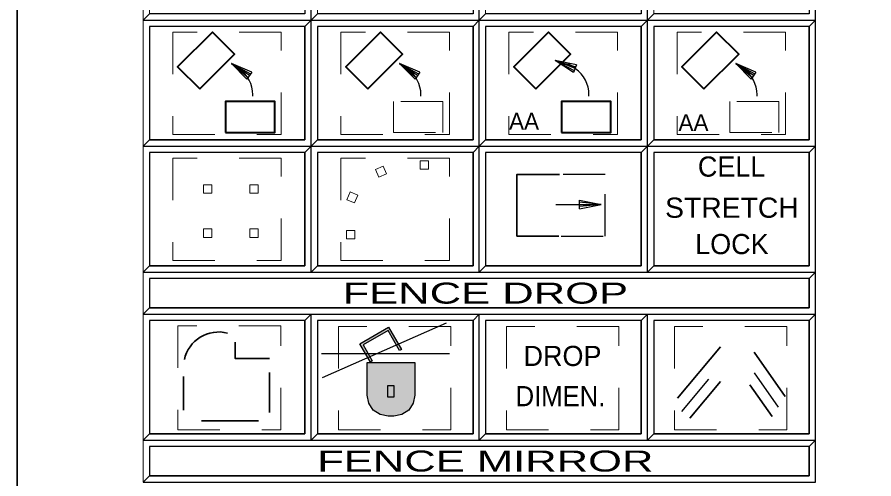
# Model space of a CAD drawing. Extents: x 95906.8 to 95923.6, y 90964.8 to 90972.8.
# Drawn here: x 95906.832 to 95908.871, y 90966.169 to 90967.269 of the extents above; entities that cross this region are included whole.
import ezdxf
from ezdxf.enums import TextEntityAlignment as Align

# ---------------------------------------------------------------- set-up
doc = ezdxf.new("R2010")
doc.units = 0
doc.header["$LTSCALE"] = 0.019
for name, pattern in [('DOT_DASHED', [7.7, 5, -1.2, 0.3, -1.2]), ('DOTTED', [1.5, 0.3, -1.2]), ('MEDIUM_DASHED', [4.5, 3, -1.5])]:
    doc.linetypes.add(name, pattern=pattern)
for name, color, linetype, lineweight in [('11', 7, 'Continuous', 25), ('12', 7, 'Continuous', 25), ('18', 7, 'Continuous', 25), ('2', 7, 'Continuous', 13), ('3', 7, 'Continuous', 25), ('6', 7, 'Continuous', 25), ('7', 7, 'Continuous', 35)]:
    doc.layers.add(name, color=color, linetype=linetype, lineweight=lineweight)

msp = doc.modelspace()

# ---------------------------------------------------------------- hatches: boundary and pattern name
at = {"layer": '6'}
for points in [[(95907.6731, 90966.4475), (95907.6478, 90966.4913), (95907.7164, 90966.5309), (95907.7471, 90966.4778), (95907.7424, 90966.4751), (95907.7152, 90966.5225), (95907.6556, 90966.4883), (95907.6776, 90966.4501)], [(95907.6653, 90966.3684), (95907.6653, 90966.4468), (95907.7788, 90966.4468), (95907.7788, 90966.3684), (95907.775, 90966.3493), (95907.7642, 90966.333), (95907.7479, 90966.3222), (95907.7288, 90966.3184), (95907.7153, 90966.3184), (95907.6962, 90966.3222), (95907.6799, 90966.333), (95907.6691, 90966.3493)], [(95907.7143, 90966.3914), (95907.7285, 90966.3914), (95907.7285, 90966.3638), (95907.7143, 90966.3638)]]:
    msp.add_hatch(color=256, dxfattribs=at).paths.add_polyline_path(points)

# ---------------------------------------------------------------- linework, layer by layer
at = {"layer": '11'}
for points in [[(95907.1473, 90966.9767), (95907.5173, 90966.9767), (95907.5173, 90967.2467), (95907.1473, 90967.2467)], [(95907.5473, 90966.9767), (95907.9173, 90966.9767), (95907.9173, 90967.2467), (95907.5473, 90967.2467)], [(95907.9473, 90966.9767), (95908.3173, 90966.9767), (95908.3173, 90967.2467), (95907.9473, 90967.2467)], [(95908.3473, 90966.9767), (95908.7173, 90966.9767), (95908.7173, 90967.2467), (95908.3473, 90967.2467)], [(95907.1473, 90966.6767), (95907.5173, 90966.6767), (95907.5173, 90966.9467), (95907.1473, 90966.9467)], [(95907.5473, 90966.6767), (95907.9173, 90966.6767), (95907.9173, 90966.9467), (95907.5473, 90966.9467)], [(95907.9473, 90966.6767), (95908.3173, 90966.6767), (95908.3173, 90966.9467), (95907.9473, 90966.9467)], [(95908.3473, 90966.6767), (95908.7173, 90966.6767), (95908.7173, 90966.9467), (95908.3473, 90966.9467)], [(95907.5473, 90966.2767), (95907.9173, 90966.2767), (95907.9173, 90966.5467), (95907.5473, 90966.5467)], [(95907.9473, 90966.2767), (95908.3173, 90966.2767), (95908.3173, 90966.5467), (95907.9473, 90966.5467)], [(95908.3473, 90966.2767), (95908.7173, 90966.2767), (95908.7173, 90966.5467), (95908.3473, 90966.5467)]]:
    msp.add_lwpolyline(points, close=True, dxfattribs=at)
at = {"layer": '12'}
msp.add_lwpolyline([(95907.1473, 90966.2767), (95907.5173, 90966.2767), (95907.5173, 90966.5467), (95907.1473, 90966.5467)], close=True, dxfattribs=at)
at = {"layer": '18'}
for points in [[(95907.1473, 90966.5767), (95908.7173, 90966.5767), (95908.7173, 90966.6467), (95907.1473, 90966.6467)], [(95907.1473, 90966.1767), (95908.7173, 90966.1767), (95908.7173, 90966.2467), (95907.1473, 90966.2467)]]:
    msp.add_lwpolyline(points, close=True, dxfattribs=at)
at = {"layer": '2'}
for points in [[(95907.1323, 90967.5617), (95907.1323, 90967.2617), (95907.1473, 90967.2767), (95907.1473, 90967.5467), (95907.5173, 90967.5467), (95907.5323, 90967.5617)], [(95907.5323, 90967.5617), (95907.5323, 90967.2617), (95907.5473, 90967.2767), (95907.5473, 90967.5467), (95907.9173, 90967.5467), (95907.9323, 90967.5617)], [(95907.9323, 90967.5617), (95907.9323, 90967.2617), (95907.9473, 90967.2767), (95907.9473, 90967.5467), (95908.3173, 90967.5467), (95908.3323, 90967.5617)], [(95908.3323, 90967.5617), (95908.3323, 90967.2617), (95908.3473, 90967.2767), (95908.3473, 90967.5467), (95908.7173, 90967.5467), (95908.7323, 90967.5617)], [(95907.1323, 90967.2617), (95907.1323, 90966.9617), (95907.1473, 90966.9767), (95907.1473, 90967.2467), (95907.5173, 90967.2467), (95907.5323, 90967.2617)], [(95907.5323, 90967.2617), (95907.5323, 90966.9617), (95907.5473, 90966.9767), (95907.5473, 90967.2467), (95907.9173, 90967.2467), (95907.9323, 90967.2617)], [(95907.9323, 90967.2617), (95907.9323, 90966.9617), (95907.9473, 90966.9767), (95907.9473, 90967.2467), (95908.3173, 90967.2467), (95908.3323, 90967.2617)], [(95908.3323, 90967.2617), (95908.3323, 90966.9617), (95908.3473, 90966.9767), (95908.3473, 90967.2467), (95908.7173, 90967.2467), (95908.7323, 90967.2617)], [(95907.1323, 90966.9617), (95907.1323, 90966.6617), (95907.1473, 90966.6767), (95907.1473, 90966.9467), (95907.5173, 90966.9467), (95907.5323, 90966.9617)], [(95907.5323, 90966.9617), (95907.5323, 90966.6617), (95907.5473, 90966.6767), (95907.5473, 90966.9467), (95907.9173, 90966.9467), (95907.9323, 90966.9617)], [(95907.9323, 90966.9617), (95907.9323, 90966.6617), (95907.9473, 90966.6767), (95907.9473, 90966.9467), (95908.3173, 90966.9467), (95908.3323, 90966.9617)], [(95908.3323, 90966.9617), (95908.3323, 90966.6617), (95908.3473, 90966.6767), (95908.3473, 90966.9467), (95908.7173, 90966.9467), (95908.7323, 90966.9617)], [(95907.1323, 90966.6617), (95907.1323, 90966.5617), (95907.1473, 90966.5767), (95907.1473, 90966.6467), (95908.7173, 90966.6467), (95908.7323, 90966.6617)], [(95907.1323, 90966.5617), (95907.1323, 90966.2617), (95907.1473, 90966.2767), (95907.1473, 90966.5467), (95907.5173, 90966.5467), (95907.5323, 90966.5617)], [(95907.5323, 90966.5617), (95907.5323, 90966.2617), (95907.5473, 90966.2767), (95907.5473, 90966.5467), (95907.9173, 90966.5467), (95907.9323, 90966.5617)], [(95907.9323, 90966.5617), (95907.9323, 90966.2617), (95907.9473, 90966.2767), (95907.9473, 90966.5467), (95908.3173, 90966.5467), (95908.3323, 90966.5617)], [(95908.3323, 90966.5617), (95908.3323, 90966.2617), (95908.3473, 90966.2767), (95908.3473, 90966.5467), (95908.7173, 90966.5467), (95908.7323, 90966.5617)], [(95907.1323, 90966.2617), (95907.1323, 90966.1617), (95907.1473, 90966.1767), (95907.1473, 90966.2467), (95908.7173, 90966.2467), (95908.7323, 90966.2617)]]:
    msp.add_lwpolyline(points, close=True, dxfattribs=at)
at = {"layer": '3'}
for points in [[(95907.1323, 90967.2617), (95907.5323, 90967.2617), (95907.5323, 90967.5617), (95907.5173, 90967.5467), (95907.5173, 90967.2767), (95907.1473, 90967.2767)], [(95907.5323, 90967.2617), (95907.9323, 90967.2617), (95907.9323, 90967.5617), (95907.9173, 90967.5467), (95907.9173, 90967.2767), (95907.5473, 90967.2767)], [(95907.9323, 90967.2617), (95908.3323, 90967.2617), (95908.3323, 90967.5617), (95908.3173, 90967.5467), (95908.3173, 90967.2767), (95907.9473, 90967.2767)], [(95908.3323, 90967.2617), (95908.7323, 90967.2617), (95908.7323, 90967.5617), (95908.7173, 90967.5467), (95908.7173, 90967.2767), (95908.3473, 90967.2767)], [(95907.1323, 90966.9617), (95907.5323, 90966.9617), (95907.5323, 90967.2617), (95907.5173, 90967.2467), (95907.5173, 90966.9767), (95907.1473, 90966.9767)], [(95907.5323, 90966.9617), (95907.9323, 90966.9617), (95907.9323, 90967.2617), (95907.9173, 90967.2467), (95907.9173, 90966.9767), (95907.5473, 90966.9767)], [(95907.9323, 90966.9617), (95908.3323, 90966.9617), (95908.3323, 90967.2617), (95908.3173, 90967.2467), (95908.3173, 90966.9767), (95907.9473, 90966.9767)], [(95908.3323, 90966.9617), (95908.7323, 90966.9617), (95908.7323, 90967.2617), (95908.7173, 90967.2467), (95908.7173, 90966.9767), (95908.3473, 90966.9767)], [(95907.1323, 90966.6617), (95907.5323, 90966.6617), (95907.5323, 90966.9617), (95907.5173, 90966.9467), (95907.5173, 90966.6767), (95907.1473, 90966.6767)], [(95907.5323, 90966.6617), (95907.9323, 90966.6617), (95907.9323, 90966.9617), (95907.9173, 90966.9467), (95907.9173, 90966.6767), (95907.5473, 90966.6767)], [(95907.9323, 90966.6617), (95908.3323, 90966.6617), (95908.3323, 90966.9617), (95908.3173, 90966.9467), (95908.3173, 90966.6767), (95907.9473, 90966.6767)], [(95908.3323, 90966.6617), (95908.7323, 90966.6617), (95908.7323, 90966.9617), (95908.7173, 90966.9467), (95908.7173, 90966.6767), (95908.3473, 90966.6767)], [(95907.1323, 90966.5617), (95908.7323, 90966.5617), (95908.7323, 90966.6617), (95908.7173, 90966.6467), (95908.7173, 90966.5767), (95907.1473, 90966.5767)], [(95907.1323, 90966.2617), (95907.5323, 90966.2617), (95907.5323, 90966.5617), (95907.5173, 90966.5467), (95907.5173, 90966.2767), (95907.1473, 90966.2767)], [(95907.5323, 90966.2617), (95907.9323, 90966.2617), (95907.9323, 90966.5617), (95907.9173, 90966.5467), (95907.9173, 90966.2767), (95907.5473, 90966.2767)], [(95907.9323, 90966.2617), (95908.3323, 90966.2617), (95908.3323, 90966.5617), (95908.3173, 90966.5467), (95908.3173, 90966.2767), (95907.9473, 90966.2767)], [(95908.3323, 90966.2617), (95908.7323, 90966.2617), (95908.7323, 90966.5617), (95908.7173, 90966.5467), (95908.7173, 90966.2767), (95908.3473, 90966.2767)], [(95907.1323, 90966.1617), (95908.7323, 90966.1617), (95908.7323, 90966.2617), (95908.7173, 90966.2467), (95908.7173, 90966.1767), (95907.1473, 90966.1767)]]:
    msp.add_lwpolyline(points, close=True, dxfattribs=at)
at = {"layer": '6'}
for p, q in [((95907.361, 90967.1461), (95907.3426, 90967.1585)), ((95907.3851, 90967.1299), (95907.3426, 90967.1585)), ((95907.3426, 90967.1585), (95907.3877, 90967.1338)), ((95907.761, 90967.1461), (95907.7426, 90967.1585)), ((95907.7851, 90967.1299), (95907.7426, 90967.1585)), ((95907.7426, 90967.1585), (95907.7877, 90967.1338)), ((95908.1601, 90967.1465), (95908.1128, 90967.1662)), ((95908.1128, 90967.1662), (95908.1619, 90967.1509)), ((95908.161, 90967.1461), (95908.1426, 90967.1585)), ((95908.561, 90967.1461), (95908.5426, 90967.1585)), ((95908.5851, 90967.1299), (95908.5426, 90967.1585)), ((95908.5426, 90967.1585), (95908.5877, 90967.1338)), ((95907.3933, 90967.081), (95907.3933, 90967.0844)), ((95907.7933, 90967.081), (95907.7933, 90967.0844)), ((95908.1933, 90967.081), (95908.1933, 90967.0844)), ((95908.5933, 90967.081), (95908.5933, 90967.0844)), ((95908.1146, 90966.823), (95908.2221, 90966.823)), ((95908.1709, 90966.823), (95908.2221, 90966.823)), ((95908.2221, 90966.823), (95908.1709, 90966.8182)), ((95907.559, 90966.4108), (95907.8542, 90966.541)), ((95907.8613, 90966.467), (95907.5569, 90966.467))]:
    msp.add_line(p, q, dxfattribs=at)
at = {"layer": '6', "lineweight": 35}
for p, q in [((95908.404, 90966.3615), (95908.5067, 90966.4839)), ((95908.5862, 90966.4713), (95908.6601, 90966.3657)), ((95907.2284, 90966.3332), (95907.2284, 90966.4131)), ((95907.4328, 90966.4223), (95907.4328, 90966.327)), ((95908.4335, 90966.3142), (95908.5067, 90966.4015)), ((95908.5763, 90966.3931), (95908.629, 90966.3178)), ((95907.4067, 90966.3071), (95907.2714, 90966.3071))]:
    msp.add_line(p, q, dxfattribs=at)
at = {"layer": '6', "linetype": 'DOT_DASHED'}
for p, q in [((95908.4147, 90966.3299), (95908.5067, 90966.4396)), ((95908.5862, 90966.4217), (95908.6491, 90966.3319))]:
    msp.add_line(p, q, dxfattribs=at)
at = {"layer": '6', "linetype": 'DOTTED', "lineweight": 13}
for points in [[(95907.2029, 90966.9893), (95907.4611, 90966.9893), (95907.4611, 90967.2332), (95907.2029, 90967.2332)], [(95907.6029, 90966.9893), (95907.8611, 90966.9893), (95907.8611, 90967.2332), (95907.6029, 90967.2332)], [(95908.0029, 90966.9893), (95908.2611, 90966.9893), (95908.2611, 90967.2332), (95908.0029, 90967.2332)], [(95908.4029, 90966.9893), (95908.6611, 90966.9893), (95908.6611, 90967.2332), (95908.4029, 90967.2332)], [(95907.2029, 90966.6893), (95907.4611, 90966.6893), (95907.4611, 90966.9332), (95907.2029, 90966.9332)], [(95907.6029, 90966.6893), (95907.8611, 90966.6893), (95907.8611, 90966.9332), (95907.6029, 90966.9332)], [(95907.2145, 90966.2863), (95907.46, 90966.2863), (95907.46, 90966.5337), (95907.2145, 90966.5337)], [(95907.8644, 90966.5322), (95907.5972, 90966.5322), (95907.5972, 90966.2858), (95907.8644, 90966.2858)], [(95908.2644, 90966.5322), (95907.9972, 90966.5322), (95907.9972, 90966.2858), (95908.2644, 90966.2858)], [(95908.6644, 90966.5322), (95908.3972, 90966.5322), (95908.3972, 90966.2858), (95908.6644, 90966.2858)]]:
    msp.add_lwpolyline(points, close=True, dxfattribs=at)
at = {"layer": '6', "lineweight": 40}
for points in [[(95907.2668, 90967.0981), (95907.3496, 90967.1809), (95907.2971, 90967.2334), (95907.2143, 90967.1506)], [(95907.6668, 90967.0981), (95907.7496, 90967.1809), (95907.6971, 90967.2334), (95907.6143, 90967.1506)], [(95908.0668, 90967.0981), (95908.1496, 90967.1809), (95908.0971, 90967.2334), (95908.0143, 90967.1506)], [(95908.4668, 90967.0981), (95908.5496, 90967.1809), (95908.4971, 90967.2334), (95908.4143, 90967.1506)], [(95907.3283, 90966.994), (95907.4454, 90966.994), (95907.4454, 90967.0683), (95907.3283, 90967.0683)], [(95908.1283, 90966.994), (95908.2454, 90966.994), (95908.2454, 90967.0683), (95908.1283, 90967.0683)]]:
    msp.add_lwpolyline(points, close=True, dxfattribs=at)
at = {"layer": '6'}
for points in [[(95907.3908, 90967.1384), (95907.3793, 90967.1214), (95907.3426, 90967.1585)], [(95907.3908, 90967.1384), (95907.3426, 90967.1585), (95907.3823, 90967.1257)], [(95907.7908, 90967.1384), (95907.7793, 90967.1214), (95907.7426, 90967.1585)], [(95907.7908, 90967.1384), (95907.7426, 90967.1585), (95907.7823, 90967.1257)], [(95908.164, 90967.1559), (95908.1561, 90967.137), (95908.1128, 90967.1662)], [(95908.164, 90967.1559), (95908.1128, 90967.1662), (95908.1581, 90967.1419)], [(95908.5908, 90967.1384), (95908.5793, 90967.1214), (95908.5426, 90967.1585)], [(95908.5908, 90967.1384), (95908.5426, 90967.1585), (95908.5823, 90967.1257)], [(95908.1709, 90966.8128), (95908.1709, 90966.8332), (95908.2221, 90966.823)], [(95908.1709, 90966.8128), (95908.2221, 90966.823), (95908.1709, 90966.828)]]:
    msp.add_lwpolyline(points, dxfattribs=at)
at = {"layer": '6', "linetype": 'MEDIUM_DASHED', "lineweight": 13}
for points in [[(95907.7283, 90966.994), (95907.8454, 90966.994), (95907.8454, 90967.0683), (95907.7283, 90967.0683)], [(95908.5283, 90966.994), (95908.6454, 90966.994), (95908.6454, 90967.0683), (95908.5283, 90967.0683)]]:
    msp.add_lwpolyline(points, close=True, dxfattribs=at)
at = {"layer": '6', "lineweight": 13}
for points in [[(95907.7115, 90966.8955), (95907.7038, 90966.914), (95907.6854, 90966.9063), (95907.693, 90966.8878)], [(95907.7912, 90966.9067), (95907.8112, 90966.9067), (95907.8112, 90966.9267), (95907.7912, 90966.9267)], [(95907.2757, 90966.8499), (95907.2957, 90966.8499), (95907.2957, 90966.8699), (95907.2757, 90966.8699)], [(95907.3861, 90966.8499), (95907.4061, 90966.8499), (95907.4061, 90966.8699), (95907.3861, 90966.8699)], [(95907.6432, 90966.845), (95907.6247, 90966.8527), (95907.6171, 90966.8342), (95907.6355, 90966.8265)], [(95907.2757, 90966.7446), (95907.2957, 90966.7446), (95907.2957, 90966.7646), (95907.2757, 90966.7646)], [(95907.3861, 90966.7446), (95907.4061, 90966.7446), (95907.4061, 90966.7646), (95907.3861, 90966.7646)], [(95907.636, 90966.7408), (95907.636, 90966.7608), (95907.616, 90966.7608), (95907.616, 90966.7408)]]:
    msp.add_lwpolyline(points, close=True, dxfattribs=at)
at = {"layer": '6', "lineweight": 35}
for points in [[(95908.1231, 90966.8944), (95908.0219, 90966.8944), (95908.0219, 90966.7474), (95908.1214, 90966.7474)], [(95907.4328, 90966.4557), (95907.3513, 90966.4557), (95907.3513, 90966.4946)]]:
    msp.add_lwpolyline(points, dxfattribs=at)
at = {"layer": '6', "linetype": 'DOTTED'}
msp.add_lwpolyline([(95908.127, 90966.7474), (95908.232, 90966.7474), (95908.232, 90966.8944), (95908.1271, 90966.8944)], dxfattribs=at)
at = {"layer": '6'}
for points in [[(95907.6731, 90966.4475), (95907.6478, 90966.4913), (95907.7164, 90966.5309), (95907.7471, 90966.4778), (95907.7424, 90966.4751), (95907.7152, 90966.5225), (95907.6556, 90966.4883), (95907.6776, 90966.4501)], [(95907.6653, 90966.3684), (95907.6653, 90966.4468), (95907.7788, 90966.4468), (95907.7788, 90966.3684), (95907.775, 90966.3493), (95907.7642, 90966.333), (95907.7479, 90966.3222), (95907.7288, 90966.3184), (95907.7153, 90966.3184), (95907.6962, 90966.3222), (95907.6799, 90966.333), (95907.6691, 90966.3493)], [(95907.7143, 90966.3914), (95907.7285, 90966.3914), (95907.7285, 90966.3638), (95907.7143, 90966.3638)]]:
    msp.add_lwpolyline(points, close=True, dxfattribs=at)
for centre in [(95907.3183, 90967.0844), (95907.7183, 90967.0844), (95908.1183, 90967.0844), (95908.5183, 90967.0844)]:
    msp.add_arc(centre, 0.075, 0, 55.2568, dxfattribs=at)
at = {"layer": '6', "lineweight": 35}
msp.add_arc((95907.3121, 90966.4354), 0.0838, 75.8303, 167.4043, dxfattribs=at)
at = {"layer": '7'}
msp.add_lwpolyline([(95906.8323, 90972.7617), (95918.8323, 90972.7617), (95918.8323, 90964.7617), (95906.8323, 90964.7617)], close=True, dxfattribs=at)

# ---------------------------------------------------------------- texts
at = {"layer": '6'}
for s, height, p in [('AA', 0.04, (95908.0388, 90967.0012)), ('AA', 0.04, (95908.442, 90966.998)), ('CELL', 0.048, (95908.5328, 90966.8892)), ('LOCK', 0.048, (95908.5335, 90966.7046)), ('DROP', 0.048, (95908.1303, 90966.4381))]:
    msp.add_text(s, height=height, dxfattribs=at).set_placement(p, align=Align.CENTER)
for s, width, p in [('STRETCH', 1.05, (95908.5335, 90966.7912)), ('DIMEN.', 0.95, (95908.1255, 90966.3423))]:
    msp.add_text(s, height=0.048, dxfattribs=dict(at, width=width)).set_placement(p, align=Align.CENTER)
at = {"layer": '7', "width": 1.55}
for s, p in [('       FENCE DROP      ', (95907.9322, 90966.5867)), ('      FENCE MIRROR     ', (95907.9322, 90966.1867))]:
    msp.add_text(s, height=0.04999, dxfattribs=at).set_placement(p, align=Align.CENTER)

doc.saveas('drawing.dxf')
